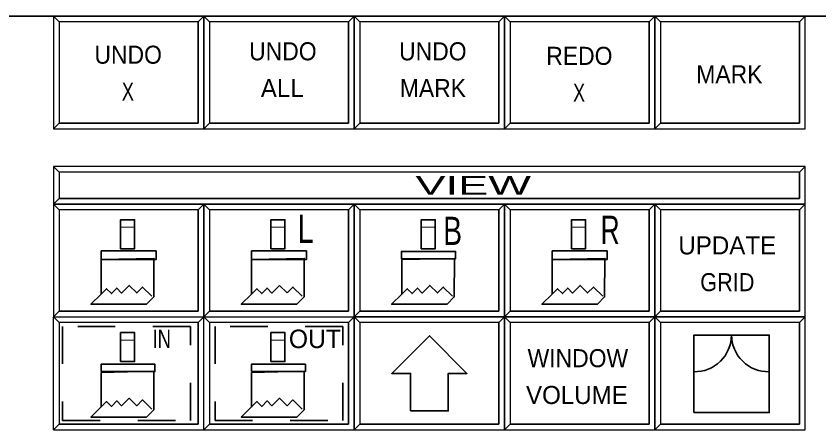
# Model space of a CAD drawing. Extents: x 95906.9 to 95918.9, y 90964.8 to 90972.9.
# Drawn here: x 95912.532 to 95914.669, y 90971.769 to 90972.862 of the extents above; entities that cross this region are included whole.
import ezdxf
from ezdxf.enums import TextEntityAlignment as Align

# ---------------------------------------------------------------- set-up
doc = ezdxf.new("R2010")
doc.units = 0
doc.header["$LTSCALE"] = 0.019
doc.linetypes.add('DOTTED', pattern=[1.5, 0.3, -1.2])
for name, color, linetype, lineweight in [('1', 7, 'Continuous', 25), ('11', 7, 'Continuous', 25), ('12', 7, 'Continuous', 25), ('2', 7, 'Continuous', 13), ('21', 7, 'Continuous', 25), ('3', 7, 'Continuous', 25), ('4', 7, 'Continuous', 35), ('6', 7, 'Continuous', 35), ('7', 7, 'Continuous', 35)]:
    doc.layers.add(name, color=color, linetype=linetype, lineweight=lineweight)

msp = doc.modelspace()

# ---------------------------------------------------------------- linework, layer by layer
at = {"layer": '1'}
msp.add_line((95912.6323, 90971.7615), (95912.6323, 90972.0615), dxfattribs=at)
for points in [[(95912.6323, 90972.5617), (95913.0323, 90972.5617), (95913.0323, 90972.8617), (95912.6323, 90972.8617)], [(95913.0323, 90972.5617), (95913.4323, 90972.5617), (95913.4323, 90972.8617), (95913.0323, 90972.8617)], [(95913.4323, 90972.5617), (95913.8323, 90972.5617), (95913.8323, 90972.8617), (95913.4323, 90972.8617)], [(95913.8323, 90972.5617), (95914.2323, 90972.5617), (95914.2323, 90972.8617), (95913.8323, 90972.8617)], [(95914.2323, 90972.5617), (95914.6323, 90972.5617), (95914.6323, 90972.8617), (95914.2323, 90972.8617)], [(95912.6323, 90972.3617), (95914.6323, 90972.3617), (95914.6323, 90972.4617), (95912.6323, 90972.4617)], [(95912.6323, 90972.0617), (95913.0323, 90972.0617), (95913.0323, 90972.3617), (95912.6323, 90972.3617)], [(95913.0323, 90972.0617), (95913.4323, 90972.0617), (95913.4323, 90972.3617), (95913.0323, 90972.3617)], [(95913.4323, 90972.0617), (95913.8323, 90972.0617), (95913.8323, 90972.3617), (95913.4323, 90972.3617)], [(95913.8323, 90972.0617), (95914.2323, 90972.0617), (95914.2323, 90972.3617), (95913.8323, 90972.3617)], [(95914.2323, 90972.0617), (95914.6323, 90972.0617), (95914.6323, 90972.3617), (95914.2323, 90972.3617)], [(95913.4323, 90971.7617), (95913.8323, 90971.7617), (95913.8323, 90972.0617), (95913.4323, 90972.0617)], [(95913.8323, 90971.7617), (95914.2323, 90971.7617), (95914.2323, 90972.0617), (95913.8323, 90972.0617)], [(95914.2323, 90971.7617), (95914.6323, 90971.7617), (95914.6323, 90972.0617), (95914.2323, 90972.0617)]]:
    msp.add_lwpolyline(points, close=True, dxfattribs=at)
at = {"layer": '11'}
for points in [[(95912.6473, 90972.5767), (95913.0173, 90972.5767), (95913.0173, 90972.8467), (95912.6473, 90972.8467)], [(95913.0473, 90972.5767), (95913.4173, 90972.5767), (95913.4173, 90972.8467), (95913.0473, 90972.8467)], [(95913.4473, 90972.5767), (95913.8173, 90972.5767), (95913.8173, 90972.8467), (95913.4473, 90972.8467)], [(95913.8473, 90972.5767), (95914.2173, 90972.5767), (95914.2173, 90972.8467), (95913.8473, 90972.8467)], [(95914.2473, 90972.5767), (95914.6173, 90972.5767), (95914.6173, 90972.8467), (95914.2473, 90972.8467)], [(95912.6473, 90972.0767), (95913.0173, 90972.0767), (95913.0173, 90972.3467), (95912.6473, 90972.3467)], [(95913.0473, 90972.0767), (95913.4173, 90972.0767), (95913.4173, 90972.3467), (95913.0473, 90972.3467)], [(95913.4473, 90972.0767), (95913.8173, 90972.0767), (95913.8173, 90972.3467), (95913.4473, 90972.3467)], [(95913.8473, 90972.0767), (95914.2173, 90972.0767), (95914.2173, 90972.3467), (95913.8473, 90972.3467)], [(95914.2473, 90972.0767), (95914.6173, 90972.0767), (95914.6173, 90972.3467), (95914.2473, 90972.3467)], [(95912.6473, 90971.7767), (95913.0173, 90971.7767), (95913.0173, 90972.0467), (95912.6473, 90972.0467)], [(95913.0473, 90971.7767), (95913.4173, 90971.7767), (95913.4173, 90972.0467), (95913.0473, 90972.0467)], [(95913.4473, 90971.7767), (95913.8173, 90971.7767), (95913.8173, 90972.0467), (95913.4473, 90972.0467)], [(95913.8473, 90971.7767), (95914.2173, 90971.7767), (95914.2173, 90972.0467), (95913.8473, 90972.0467)], [(95914.2473, 90971.7767), (95914.6173, 90971.7767), (95914.6173, 90972.0467), (95914.2473, 90972.0467)]]:
    msp.add_lwpolyline(points, close=True, dxfattribs=at)
at = {"layer": '12'}
for points in [[(95912.6473, 90972.0767), (95913.0173, 90972.0767), (95913.0173, 90972.3467), (95912.6473, 90972.3467)], [(95913.0473, 90972.0767), (95913.4173, 90972.0767), (95913.4173, 90972.3467), (95913.0473, 90972.3467)], [(95913.4473, 90972.0767), (95913.8173, 90972.0767), (95913.8173, 90972.3467), (95913.4473, 90972.3467)], [(95913.8473, 90972.0767), (95914.2173, 90972.0767), (95914.2173, 90972.3467), (95913.8473, 90972.3467)], [(95912.6473, 90971.7767), (95913.0173, 90971.7767), (95913.0173, 90972.0467), (95912.6473, 90972.0467)], [(95913.0473, 90971.7767), (95913.4173, 90971.7767), (95913.4173, 90972.0467), (95913.0473, 90972.0467)], [(95914.2473, 90971.7767), (95914.6173, 90971.7767), (95914.6173, 90972.0467), (95914.2473, 90972.0467)]]:
    msp.add_lwpolyline(points, close=True, dxfattribs=at)
at = {"layer": '2'}
for points in [[(95912.6323, 90972.8617), (95912.6323, 90972.5617), (95912.6473, 90972.5767), (95912.6473, 90972.8467), (95913.0173, 90972.8467), (95913.0323, 90972.8617)], [(95913.0323, 90972.8617), (95913.0323, 90972.5617), (95913.0473, 90972.5767), (95913.0473, 90972.8467), (95913.4173, 90972.8467), (95913.4323, 90972.8617)], [(95913.4323, 90972.8617), (95913.4323, 90972.5617), (95913.4473, 90972.5767), (95913.4473, 90972.8467), (95913.8173, 90972.8467), (95913.8323, 90972.8617)], [(95913.8323, 90972.8617), (95913.8323, 90972.5617), (95913.8473, 90972.5767), (95913.8473, 90972.8467), (95914.2173, 90972.8467), (95914.2323, 90972.8617)], [(95914.2323, 90972.8617), (95914.2323, 90972.5617), (95914.2473, 90972.5767), (95914.2473, 90972.8467), (95914.6173, 90972.8467), (95914.6323, 90972.8617)], [(95912.6323, 90972.4617), (95912.6323, 90972.3617), (95912.6473, 90972.3767), (95912.6473, 90972.4467), (95914.6173, 90972.4467), (95914.6323, 90972.4617)], [(95912.6323, 90972.3617), (95912.6323, 90972.0617), (95912.6473, 90972.0767), (95912.6473, 90972.3467), (95913.0173, 90972.3467), (95913.0323, 90972.3617)], [(95913.0323, 90972.3617), (95913.0323, 90972.0617), (95913.0473, 90972.0767), (95913.0473, 90972.3467), (95913.4173, 90972.3467), (95913.4323, 90972.3617)], [(95913.4323, 90972.3617), (95913.4323, 90972.0617), (95913.4473, 90972.0767), (95913.4473, 90972.3467), (95913.8173, 90972.3467), (95913.8323, 90972.3617)], [(95913.4323, 90972.3617), (95913.4323, 90972.0617), (95913.4473, 90972.0767), (95913.4473, 90972.3467), (95913.8173, 90972.3467), (95913.8323, 90972.3617)], [(95913.4323, 90972.3617), (95913.4323, 90972.0617), (95913.4473, 90972.0767), (95913.4473, 90972.3467), (95913.8173, 90972.3467), (95913.8323, 90972.3617)], [(95913.8323, 90972.3617), (95913.8323, 90972.0617), (95913.8473, 90972.0767), (95913.8473, 90972.3467), (95914.2173, 90972.3467), (95914.2323, 90972.3617)], [(95914.2323, 90972.3617), (95914.2323, 90972.0617), (95914.2473, 90972.0767), (95914.2473, 90972.3467), (95914.6173, 90972.3467), (95914.6323, 90972.3617)], [(95912.6323, 90972.0617), (95912.6323, 90971.7617), (95912.6473, 90971.7767), (95912.6473, 90972.0467), (95913.0173, 90972.0467), (95913.0323, 90972.0617)], [(95913.0323, 90972.0617), (95913.0323, 90971.7617), (95913.0473, 90971.7767), (95913.0473, 90972.0467), (95913.4173, 90972.0467), (95913.4323, 90972.0617)], [(95913.4323, 90972.0617), (95913.4323, 90971.7617), (95913.4473, 90971.7767), (95913.4473, 90972.0467), (95913.8173, 90972.0467), (95913.8323, 90972.0617)], [(95913.8323, 90972.0617), (95913.8323, 90971.7617), (95913.8473, 90971.7767), (95913.8473, 90972.0467), (95914.2173, 90972.0467), (95914.2323, 90972.0617)], [(95914.2323, 90972.0617), (95914.2323, 90971.7617), (95914.2473, 90971.7767), (95914.2473, 90972.0467), (95914.6173, 90972.0467), (95914.6323, 90972.0617)]]:
    msp.add_lwpolyline(points, close=True, dxfattribs=at)
at = {"layer": '21'}
msp.add_lwpolyline([(95912.6473, 90972.3767), (95914.6173, 90972.3767), (95914.6173, 90972.4467), (95912.6473, 90972.4467)], close=True, dxfattribs=at)
at = {"layer": '3'}
for points in [[(95912.6323, 90972.5617), (95913.0323, 90972.5617), (95913.0323, 90972.8617), (95913.0173, 90972.8467), (95913.0173, 90972.5767), (95912.6473, 90972.5767)], [(95913.0323, 90972.5617), (95913.4323, 90972.5617), (95913.4323, 90972.8617), (95913.4173, 90972.8467), (95913.4173, 90972.5767), (95913.0473, 90972.5767)], [(95913.4323, 90972.5617), (95913.8323, 90972.5617), (95913.8323, 90972.8617), (95913.8173, 90972.8467), (95913.8173, 90972.5767), (95913.4473, 90972.5767)], [(95913.8323, 90972.5617), (95914.2323, 90972.5617), (95914.2323, 90972.8617), (95914.2173, 90972.8467), (95914.2173, 90972.5767), (95913.8473, 90972.5767)], [(95914.2323, 90972.5617), (95914.6323, 90972.5617), (95914.6323, 90972.8617), (95914.6173, 90972.8467), (95914.6173, 90972.5767), (95914.2473, 90972.5767)], [(95912.6323, 90972.3617), (95914.6323, 90972.3617), (95914.6323, 90972.4617), (95914.6173, 90972.4467), (95914.6173, 90972.3767), (95912.6473, 90972.3767)], [(95912.6323, 90972.0617), (95913.0323, 90972.0617), (95913.0323, 90972.3617), (95913.0173, 90972.3467), (95913.0173, 90972.0767), (95912.6473, 90972.0767)], [(95913.0323, 90972.0617), (95913.4323, 90972.0617), (95913.4323, 90972.3617), (95913.4173, 90972.3467), (95913.4173, 90972.0767), (95913.0473, 90972.0767)], [(95913.4323, 90972.0617), (95913.8323, 90972.0617), (95913.8323, 90972.3617), (95913.8173, 90972.3467), (95913.8173, 90972.0767), (95913.4473, 90972.0767)], [(95913.8323, 90972.0617), (95914.2323, 90972.0617), (95914.2323, 90972.3617), (95914.2173, 90972.3467), (95914.2173, 90972.0767), (95913.8473, 90972.0767)], [(95914.2323, 90972.0617), (95914.6323, 90972.0617), (95914.6323, 90972.3617), (95914.6173, 90972.3467), (95914.6173, 90972.0767), (95914.2473, 90972.0767)], [(95912.6323, 90971.7617), (95913.0323, 90971.7617), (95913.0323, 90972.0617), (95913.0173, 90972.0467), (95913.0173, 90971.7767), (95912.6473, 90971.7767)], [(95913.0323, 90971.7617), (95913.4323, 90971.7617), (95913.4323, 90972.0617), (95913.4173, 90972.0467), (95913.4173, 90971.7767), (95913.0473, 90971.7767)], [(95913.4323, 90971.7617), (95913.8323, 90971.7617), (95913.8323, 90972.0617), (95913.8173, 90972.0467), (95913.8173, 90971.7767), (95913.4473, 90971.7767)], [(95913.8323, 90971.7617), (95914.2323, 90971.7617), (95914.2323, 90972.0617), (95914.2173, 90972.0467), (95914.2173, 90971.7767), (95913.8473, 90971.7767)], [(95914.2323, 90971.7617), (95914.6323, 90971.7617), (95914.6323, 90972.0617), (95914.6173, 90972.0467), (95914.6173, 90971.7767), (95914.2473, 90971.7767)]]:
    msp.add_lwpolyline(points, close=True, dxfattribs=at)
at = {"layer": '4'}
for p, q in [((95912.6473, 90972.8467), (95912.6323, 90972.8617)), ((95913.0473, 90972.8467), (95913.0323, 90972.8617)), ((95913.4473, 90972.8467), (95913.4323, 90972.8617)), ((95913.8473, 90972.8467), (95913.8323, 90972.8617)), ((95914.2473, 90972.8467), (95914.2323, 90972.8617)), ((95912.6473, 90972.4467), (95912.6323, 90972.4617)), ((95912.6473, 90972.3467), (95912.6323, 90972.3617)), ((95913.0473, 90972.3467), (95913.0323, 90972.3617)), ((95913.4473, 90972.3467), (95913.4323, 90972.3617)), ((95913.8473, 90972.3467), (95913.8323, 90972.3617)), ((95914.2473, 90972.3467), (95914.2323, 90972.3617)), ((95912.6473, 90972.0467), (95912.6323, 90972.0617)), ((95913.0473, 90972.0467), (95913.0323, 90972.0617)), ((95913.4473, 90972.0467), (95913.4323, 90972.0617)), ((95913.8473, 90972.0467), (95913.8323, 90972.0617)), ((95914.2473, 90972.0467), (95914.2323, 90972.0617))]:
    msp.add_line(p, q, dxfattribs=at)
at = {"layer": '6'}
msp.add_line((95913.2334, 90972.1454), (95913.2534, 90972.1254), dxfattribs=at)
for points in [[(95912.8105, 90972.2428), (95912.8477, 90972.2428), (95912.8477, 90972.3202), (95912.8105, 90972.3202)], [(95913.2105, 90972.2428), (95913.2477, 90972.2428), (95913.2477, 90972.3202), (95913.2105, 90972.3202)], [(95913.6105, 90972.2428), (95913.6477, 90972.2428), (95913.6477, 90972.3202), (95913.6105, 90972.3202)], [(95914.0105, 90972.2428), (95914.0477, 90972.2428), (95914.0477, 90972.3202), (95914.0105, 90972.3202)], [(95912.7589, 90972.2371), (95912.905, 90972.2371), (95912.905, 90972.2142), (95912.7589, 90972.2142)], [(95913.1589, 90972.2371), (95913.305, 90972.2371), (95913.305, 90972.2142), (95913.1589, 90972.2142)], [(95913.5582, 90972.2166), (95913.7018, 90972.2166), (95913.7018, 90972.2359), (95913.5582, 90972.2359)], [(95913.9589, 90972.2371), (95914.105, 90972.2371), (95914.105, 90972.2142), (95913.9589, 90972.2142)], [(95912.7589, 90972.2142), (95912.7589, 90972.1225), (95912.7317, 90972.0953), (95912.8792, 90972.0953), (95912.8986, 90972.1147), (95912.8993, 90972.2171)], [(95913.1589, 90972.2142), (95913.1589, 90972.1225), (95913.1317, 90972.0953), (95913.2792, 90972.0953), (95913.2986, 90972.1147), (95913.2993, 90972.2171)], [(95913.5589, 90972.2142), (95913.5589, 90972.1225), (95913.5317, 90972.0953), (95913.6792, 90972.0953), (95913.6986, 90972.1147), (95913.6993, 90972.2171)], [(95913.9589, 90972.2142), (95913.9589, 90972.1225), (95913.9317, 90972.0953), (95914.0792, 90972.0953), (95914.0986, 90972.1147), (95914.0993, 90972.2171)], [(95912.8105, 90971.9428), (95912.8477, 90971.9428), (95912.8477, 90972.0202), (95912.8105, 90972.0202)], [(95913.2105, 90971.9428), (95913.2477, 90971.9428), (95913.2477, 90972.0202), (95913.2105, 90972.0202)], [(95913.5823, 90971.8117), (95913.5823, 90971.9117), (95913.5323, 90971.9117), (95913.6323, 90972.0117), (95913.7323, 90971.9117), (95913.6823, 90971.9117), (95913.6823, 90971.8117)], [(95914.336, 90971.8072), (95914.5365, 90971.8072), (95914.5365, 90972.0134), (95914.336, 90972.0134)], [(95912.7584, 90971.9165), (95912.902, 90971.9165), (95912.902, 90971.9358), (95912.7584, 90971.9358)], [(95913.1588, 90971.9165), (95913.3024, 90971.9165), (95913.3024, 90971.9358), (95913.1588, 90971.9358)], [(95912.7589, 90971.9142), (95912.7589, 90971.8225), (95912.7317, 90971.7953), (95912.8792, 90971.7953), (95912.8986, 90971.8147), (95912.8993, 90971.9171)], [(95913.1589, 90971.9142), (95913.1589, 90971.8225), (95913.1317, 90971.7953), (95913.2792, 90971.7953), (95913.2986, 90971.8147), (95913.2993, 90971.9171)]]:
    msp.add_lwpolyline(points, close=True, dxfattribs=at)
at = {"layer": '6', "lineweight": 13}
for points in [[(95912.8477, 90972.3202), (95912.8105, 90972.3202), (95912.8105, 90972.3001), (95912.8477, 90972.3001)], [(95913.2477, 90972.3202), (95913.2105, 90972.3202), (95913.2105, 90972.3001), (95913.2477, 90972.3001)], [(95913.6477, 90972.3202), (95913.6105, 90972.3202), (95913.6105, 90972.3001), (95913.6477, 90972.3001)], [(95914.0477, 90972.3202), (95914.0105, 90972.3202), (95914.0105, 90972.3001), (95914.0477, 90972.3001)], [(95912.8477, 90972.0202), (95912.8105, 90972.0202), (95912.8105, 90972.0001), (95912.8477, 90972.0001)], [(95913.2477, 90972.0202), (95913.2105, 90972.0202), (95913.2105, 90972.0001), (95913.2477, 90972.0001)]]:
    msp.add_lwpolyline(points, close=True, dxfattribs=at)
at = {"layer": '6'}
for points in [[(95912.7589, 90972.1225), (95912.7732, 90972.1368), (95912.7861, 90972.1239), (95912.8004, 90972.1382), (95912.8133, 90972.1253), (95912.8334, 90972.1454), (95912.8534, 90972.1254), (95912.8691, 90972.1411), (95912.8935, 90972.1167)], [(95913.1589, 90972.1225), (95913.1732, 90972.1368), (95913.1861, 90972.1239), (95913.2004, 90972.1382), (95913.2133, 90972.1253), (95913.2334, 90972.1454)], [(95913.2534, 90972.1254), (95913.2691, 90972.1411), (95913.2935, 90972.1167)], [(95913.5589, 90972.1225), (95913.5732, 90972.1368), (95913.5861, 90972.1239), (95913.6004, 90972.1382), (95913.6133, 90972.1253), (95913.6334, 90972.1454), (95913.6534, 90972.1254), (95913.6691, 90972.1411), (95913.6935, 90972.1167)], [(95913.9589, 90972.1225), (95913.9732, 90972.1368), (95913.9861, 90972.1239), (95914.0004, 90972.1382), (95914.0133, 90972.1253), (95914.0334, 90972.1454), (95914.0534, 90972.1254), (95914.0691, 90972.1411), (95914.0935, 90972.1167)], [(95912.7589, 90971.8225), (95912.7732, 90971.8368), (95912.7861, 90971.8239), (95912.8004, 90971.8382), (95912.8133, 90971.8253), (95912.8334, 90971.8454), (95912.8534, 90971.8254), (95912.8691, 90971.8411), (95912.8935, 90971.8167)], [(95913.1589, 90971.8225), (95913.1732, 90971.8368), (95913.1861, 90971.8239), (95913.2004, 90971.8382), (95913.2133, 90971.8253), (95913.2334, 90971.8454), (95913.2534, 90971.8254), (95913.2691, 90971.8411), (95913.2935, 90971.8167)]]:
    msp.add_lwpolyline(points, dxfattribs=at)
at = {"layer": '6', "linetype": 'DOTTED'}
for points in [[(95912.9964, 90972.0366), (95912.6563, 90972.0366), (95912.6563, 90971.7862), (95912.9964, 90971.7862)], [(95913.402, 90972.0366), (95913.0619, 90972.0366), (95913.0619, 90971.7862), (95913.402, 90971.7862)]]:
    msp.add_lwpolyline(points, close=True, dxfattribs=at)
at = {"layer": '6'}
for centre, start, end in [((95914.3383, 90972.014), 268.6755, 359.6437), ((95914.5343, 90972.014), 180.3563, 271.3245)]:
    msp.add_arc(centre, 0.098, start, end, dxfattribs=at)
at = {"layer": '7'}
msp.add_lwpolyline([(95906.8548, 90972.8617), (95918.8548, 90972.8617), (95918.8548, 90964.7617), (95906.8548, 90964.7617)], close=True, dxfattribs=at)

# ---------------------------------------------------------------- texts
at = {"layer": '6'}
for s, height, width, p in [('UNDO', 0.048, 0.95, (95912.8307, 90972.735)), ('UNDO', 0.048, 0.95, (95913.2423, 90972.7441)), ('UNDO', 0.048, 0.95, (95913.6414, 90972.744)), ('REDO', 0.048, 0.95, (95914.0314, 90972.7319)), ('MARK', 0.048, 0.95, (95914.4306, 90972.6829)), ('X', 0.048, 0.75, (95912.8299, 90972.637)), ('MARK', 0.048, 0.95, (95913.6416, 90972.6462)), ('X', 0.048, 0.75, (95914.0306, 90972.6339)), ('L', 0.075, 0.75, (95913.303, 90972.2586)), ('B', 0.075, 0.75, (95913.6941, 90972.2531)), ('R', 0.075, 0.7, (95914.1132, 90972.2558)), ('GRID', 0.048, 0.9, (95914.4252, 90972.1302)), ('IN', 0.0491, 0.75, (95912.92, 90971.9789)), ('WINDOW', 0.048, 0.95, (95914.0274, 90971.928))]:
    msp.add_text(s, height=height, dxfattribs=dict(at, width=width)).set_placement(p, align=Align.CENTER)
for s, height, p in [('ALL', 0.048, (95913.2407, 90972.6461)), ('UPDATE', 0.048, (95914.4249, 90972.228)), ('OUT', 0.0491, (95913.3276, 90971.9789)), ('VOLUME', 0.048, (95914.0249, 90971.8302))]:
    msp.add_text(s, height=height, dxfattribs=at).set_placement(p, align=Align.CENTER)
at = {"layer": '7', "width": 1.8}
msp.add_text('          VIEW         ', height=0.04999, dxfattribs=at).set_placement((95913.7322, 90972.3867), align=Align.CENTER)

doc.saveas('drawing.dxf')
